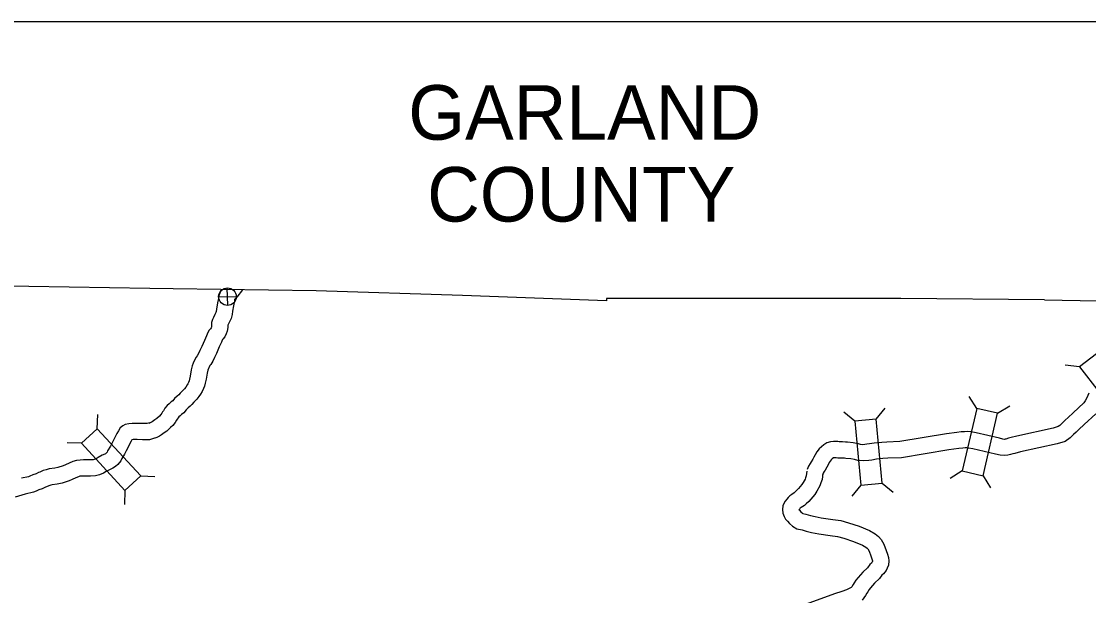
# Model space of a CAD drawing. Extents: x 1373862 to 1377080, y 1164775 to 1170415.
# Drawn here: x 1374006.5 to 1374204.1, y 1170282.4 to 1170388.8 of the extents above; entities that cross this region are included whole.
import ezdxf

# ---------------------------------------------------------------- set-up
doc = ezdxf.new("R2010")
doc.units = 0
doc.layers.add('1', color=7, linetype='Continuous')
doc.layers.add('Default', color=7, linetype='Continuous')

msp = doc.modelspace()

# ---------------------------------------------------------------- linework, layer by layer
at = {"layer": '1'}
msp.add_lwpolyline([(1373884.49, 1170388.77), (1374613.88, 1170388.77), (1374613.88, 1169861.94), (1373884.49, 1169861.94)], close=True, dxfattribs=at)
at = {"layer": 'Default'}
for p, q in [((1374044.67, 1170336.14), (1374044.59, 1170339.39)), ((1374043, 1170337.73), (1374046.26, 1170337.8)), ((1374202.39, 1170324.77), (1374199.77, 1170325.11)), ((1374183.39, 1170317.06), (1374181.99, 1170319.3)), ((1374160.79, 1170314.69), (1374158.76, 1170316.37)), ((1374164.74, 1170315.06), (1374166.42, 1170317.09)), ((1374187.24, 1170316.16), (1374189.49, 1170317.56)), ((1374020.51, 1170313.3), (1374020.61, 1170315.94)), ((1374017.6, 1170310.62), (1374014.96, 1170310.72)), ((1374028.56, 1170304.57), (1374031.2, 1170304.47)), ((1374180.69, 1170305.49), (1374178.45, 1170304.1)), ((1374184.55, 1170304.59), (1374185.94, 1170302.35)), ((1374161.9, 1170302.86), (1374160.22, 1170300.83)), ((1374165.85, 1170303.23), (1374167.88, 1170301.54)), ((1374025.65, 1170301.89), (1374025.55, 1170299.25))]:
    msp.add_line(p, q, dxfattribs=at)
for points in [[(1374030.27, 1170339.27), (1374007.88, 1170339.67), (1373981.34, 1170339.86), (1373952.41, 1170339.64), (1373952.43, 1170340.29), (1373926.15, 1170339.86), (1373899.6, 1170339.6), (1373884.49, 1170339.59)], [(1374043.63, 1170339.11), (1374043.44, 1170338.92), (1374043.21, 1170338.44), (1374043.09, 1170338.13), (1374043, 1170337.72), (1374042.96, 1170337.45), (1374042.78, 1170336.62), (1374042.59, 1170335.46), (1374042.55, 1170335.03), (1374042.48, 1170334.81), (1374042.31, 1170334.45), (1374042.04, 1170333.94), (1374041.85, 1170333.54), (1374041.69, 1170332.97), (1374041.68, 1170332.53), (1374041.69, 1170332.24), (1374041.67, 1170332.13), (1374041.67, 1170332.12), (1374041.59, 1170331.97), (1374041.48, 1170331.83), (1374041.24, 1170331.55), (1374041.01, 1170331.16), (1374040.88, 1170330.84), (1374040.75, 1170330.52), (1374040.36, 1170329.67), (1374040.13, 1170329.11), (1374039.86, 1170328.55), (1374039.51, 1170327.78), (1374039.26, 1170327.26), (1374038.99, 1170326.81), (1374038.83, 1170326.57), (1374038.46, 1170325.91), (1374038.27, 1170325.46), (1374038.11, 1170324.94), (1374037.93, 1170324.21), (1374037.74, 1170323.04), (1374037.63, 1170322.5), (1374037.53, 1170322.18), (1374037.41, 1170321.85), (1374037.31, 1170321.63), (1374037.17, 1170321.41), (1374036.9, 1170321.03), (1374036.65, 1170320.71), (1374036.27, 1170320.28), (1374035.88, 1170319.9), (1374035.6, 1170319.59), (1374035.32, 1170319.33), (1374034.85, 1170318.88), (1374034.49, 1170318.49), (1374034.22, 1170318.28), (1374033.81, 1170317.92), (1374033.46, 1170317.58), (1374033.06, 1170317.1), (1374032.77, 1170316.65), (1374032.63, 1170316.41), (1374032.49, 1170316.19), (1374032.28, 1170315.93), (1374032.02, 1170315.66), (1374031.54, 1170315.23), (1374031.18, 1170314.98), (1374030.67, 1170314.59), (1374030.56, 1170314.52), (1374030.29, 1170314.4), (1374030.04, 1170314.29)], [(1374195.9, 1170337.17), (1374169.32, 1170337.44), (1374142.6, 1170337.4), (1374114.83, 1170337.46), (1374114.82, 1170337), (1374088.12, 1170338.01), (1374061.06, 1170338.87), (1374034.57, 1170339.21), (1374030.27, 1170339.27)], [(1374047.43, 1170339.06), (1374046.37, 1170337.66), (1374045.96, 1170337.22), (1374045.95, 1170337.18), (1374045.92, 1170336.93), (1374045.73, 1170336.06), (1374045.56, 1170335.07), (1374045.51, 1170334.45), (1374045.29, 1170333.73), (1374045, 1170333.11), (1374044.73, 1170332.6), (1374044.68, 1170332.5), (1374044.69, 1170332.07), (1374044.6, 1170331.39), (1374044.41, 1170330.9), (1374044.12, 1170330.34), (1374043.79, 1170329.92), (1374043.7, 1170329.81), (1374043.67, 1170329.73), (1374043.51, 1170329.34), (1374043.12, 1170328.48), (1374042.87, 1170327.87), (1374042.57, 1170327.27), (1374042.23, 1170326.51), (1374041.9, 1170325.84), (1374041.53, 1170325.21), (1374041.38, 1170324.99), (1374041.16, 1170324.59), (1374041.09, 1170324.44), (1374041, 1170324.14), (1374040.88, 1170323.62), (1374040.69, 1170322.48), (1374040.53, 1170321.74), (1374040.37, 1170321.21), (1374040.19, 1170320.73), (1374039.96, 1170320.2), (1374039.65, 1170319.73), (1374039.32, 1170319.26), (1374038.96, 1170318.79), (1374038.43, 1170318.2), (1374038.04, 1170317.82), (1374037.75, 1170317.5), (1374037.38, 1170317.15), (1374036.99, 1170316.78), (1374036.53, 1170316.27), (1374036.13, 1170315.97), (1374035.85, 1170315.72), (1374035.65, 1170315.53), (1374035.49, 1170315.33), (1374035.33, 1170315.08), (1374035.2, 1170314.87), (1374034.95, 1170314.45), (1374034.52, 1170313.93), (1374034.11, 1170313.51), (1374033.39, 1170312.86), (1374032.93, 1170312.54), (1374032.42, 1170312.15), (1374032.03, 1170311.9), (1374031.53, 1170311.66), (1374031.27, 1170311.55)], [(1374195.9, 1170337.17), (1374218.92, 1170336.75)], [(1374204.15, 1170319.92), (1374203.94, 1170319.45), (1374203.71, 1170318.93), (1374203.47, 1170318.5), (1374203.18, 1170318.08), (1374201.23, 1170316.28), (1374200.28, 1170315.38), (1374199.71, 1170314.88), (1374199.18, 1170314.33), (1374198.76, 1170313.93), (1374198.42, 1170313.69), (1374197.5, 1170313.42), (1374190.79, 1170311.92), (1374189.77, 1170311.67), (1374189.22, 1170311.55), (1374188.76, 1170311.39), (1374188.64, 1170311.36), (1374188.47, 1170311.34), (1374188.19, 1170311.36), (1374187.58, 1170311.53), (1374183.23, 1170312.54), (1374182.26, 1170312.7), (1374181.67, 1170312.77), (1374181.08, 1170312.75), (1374180.51, 1170312.71), (1374179.7, 1170312.61), (1374177.76, 1170312.37), (1374169.13, 1170310.93), (1374166.74, 1170310.82), (1374165.78, 1170310.76), (1374165.09, 1170310.71), (1374164.36, 1170310.63), (1374163.53, 1170310.48), (1374163.03, 1170310.44), (1374162.27, 1170310.34), (1374161.87, 1170310.36), (1374161.48, 1170310.49), (1374160.47, 1170310.68), (1374159.45, 1170310.79), (1374159.06, 1170310.83), (1374158.51, 1170310.85), (1374157.89, 1170310.88), (1374157.63, 1170310.94), (1374156.84, 1170310.94), (1374156.27, 1170310.89), (1374155.62, 1170310.71), (1374155.05, 1170310.31), (1374154.62, 1170309.98), (1374154.2, 1170309.59), (1374153.76, 1170309.04), (1374153.42, 1170308.48), (1374153.19, 1170308.02), (1374153, 1170307.68), (1374152.71, 1170307.2), (1374152.52, 1170306.89), (1374152.22, 1170306.36), (1374151.99, 1170305.75)], [(1374030.5, 1170314.47), (1374029.79, 1170314.27), (1374028.96, 1170314.27), (1374027.91, 1170314.3), (1374027, 1170314.29), (1374026.39, 1170314.23), (1374025.67, 1170314.08), (1374025.27, 1170313.87), (1374024.79, 1170313.48), (1374024.43, 1170312.91), (1374024.15, 1170312.42), (1374023.21, 1170310.55), (1374022.97, 1170310.07), (1374022.43, 1170309.2), (1374022.33, 1170308.98), (1374022.16, 1170308.79), (1374022.04, 1170308.68), (1374021.95, 1170308.62), (1374021.46, 1170308.39), (1374020.72, 1170308), (1374020.31, 1170307.76), (1374019.97, 1170307.6), (1374019.79, 1170307.57), (1374019.18, 1170307.54), (1374018, 1170307.53), (1374017.33, 1170307.5), (1374016.69, 1170307.45), (1374015.98, 1170307.22), (1374015.34, 1170306.94), (1374014.64, 1170306.63), (1374014.21, 1170306.44), (1374013.24, 1170306.1), (1374012.67, 1170305.98), (1374011.6, 1170305.89), (1374011.06, 1170305.72), (1374010.52, 1170305.55), (1374009.88, 1170305.28), (1374009.67, 1170305.18), (1374009.18, 1170304.97), (1374008.61, 1170304.75), (1374008.05, 1170304.53), (1374007.8, 1170304.42), (1374006.51, 1170304.13)], [(1374205.44, 1170316.09), (1374203.28, 1170314.09), (1374202.3, 1170313.16), (1374201.77, 1170312.69), (1374201.3, 1170312.22), (1374200.67, 1170311.6), (1374199.72, 1170310.95), (1374198.26, 1170310.52), (1374191.47, 1170309), (1374190.43, 1170308.74), (1374190.04, 1170308.66), (1374189.6, 1170308.51), (1374189.15, 1170308.4), (1374188.55, 1170308.33), (1374187.69, 1170308.39), (1374186.85, 1170308.62), (1374182.64, 1170309.6), (1374181.85, 1170309.73), (1374181.53, 1170309.76), (1374181.23, 1170309.76), (1374180.81, 1170309.72), (1374180.06, 1170309.63), (1374178.19, 1170309.4), (1374169.44, 1170307.94), (1374166.9, 1170307.83), (1374165.99, 1170307.77), (1374165.38, 1170307.72), (1374164.78, 1170307.66), (1374163.93, 1170307.51), (1374163.36, 1170307.45), (1374162.38, 1170307.33), (1374161.33, 1170307.39), (1374160.73, 1170307.58), (1374160.03, 1170307.71), (1374159.14, 1170307.81), (1374158.85, 1170307.84), (1374158.39, 1170307.86), (1374157.65, 1170307.88), (1374157.34, 1170307.92), (1374157.25, 1170307.94), (1374156.99, 1170307.94), (1374156.88, 1170307.93), (1374156.83, 1170307.9), (1374156.57, 1170307.7), (1374156.42, 1170307.56), (1374156.23, 1170307.32), (1374156.05, 1170307.02), (1374155.84, 1170306.6), (1374155.59, 1170306.16), (1374155.27, 1170305.64), (1374155.1, 1170305.36), (1374154.95, 1170305.09), (1374154.8, 1170304.69)], [(1374031.32, 1170311.59), (1374030.2, 1170311.27), (1374028.92, 1170311.27), (1374027.88, 1170311.3), (1374027.17, 1170311.3), (1374026.95, 1170311.27), (1374026.81, 1170311.01), (1374025.89, 1170309.2), (1374025.59, 1170308.61), (1374025.08, 1170307.78), (1374024.87, 1170307.33), (1374024.3, 1170306.69), (1374023.92, 1170306.33), (1374023.43, 1170306), (1374022.78, 1170305.7), (1374022.18, 1170305.38), (1374021.7, 1170305.1), (1374020.93, 1170304.74), (1374020.18, 1170304.58), (1374019.26, 1170304.54), (1374018.07, 1170304.53), (1374017.52, 1170304.51), (1374017.28, 1170304.49), (1374017.04, 1170304.41), (1374016.55, 1170304.19), (1374015.87, 1170303.89), (1374015.33, 1170303.65), (1374014.04, 1170303.2), (1374013.11, 1170303.01), (1374012.18, 1170302.93), (1374011.95, 1170302.86), (1374011.56, 1170302.73), (1374011.1, 1170302.54), (1374010.91, 1170302.45), (1374010.32, 1170302.2), (1374009.71, 1170301.96), (1374009.2, 1170301.76), (1374008.74, 1170301.55), (1374007.15, 1170301.2)], [(1374151.91, 1170305.45), (1374151.79, 1170304.59), (1374151.66, 1170304.19), (1374151.58, 1170303.95), (1374151.24, 1170303.33), (1374150.98, 1170302.97), (1374150.38, 1170302.23), (1374150.14, 1170301.97), (1374149.72, 1170301.59), (1374149.56, 1170301.44), (1374149.13, 1170301.15), (1374148.78, 1170300.88), (1374148.43, 1170300.56), (1374148.18, 1170300.28), (1374147.88, 1170299.86), (1374147.63, 1170299.43), (1374147.47, 1170299), (1374147.37, 1170298.37), (1374147.46, 1170297.65), (1374147.68, 1170297.07), (1374147.97, 1170296.58), (1374148.33, 1170296.16), (1374148.71, 1170295.76), (1374149.25, 1170295.28), (1374150.04, 1170294.77), (1374151.02, 1170294.58), (1374151.77, 1170294.36), (1374152.8, 1170294.1), (1374154.1, 1170293.86), (1374156.24, 1170293.55), (1374157.58, 1170293.34), (1374158.75, 1170293.02), (1374160.55, 1170292.43), (1374162.2, 1170291.74), (1374162.85, 1170291.38), (1374163.07, 1170291.19), (1374163.22, 1170291.03), (1374163.45, 1170290.64), (1374163.78, 1170289.78), (1374163.95, 1170289.2), (1374164.06, 1170288.83), (1374164.07, 1170288.76), (1374164.07, 1170288.74), (1374164.02, 1170288.65), (1374163.86, 1170288.43), (1374163.56, 1170288.14), (1374163.12, 1170287.56), (1374162.29, 1170286.75), (1374161.4, 1170285.76), (1374161, 1170285.26), (1374160.69, 1170284.76), (1374160.47, 1170284.46), (1374160.22, 1170284.03), (1374160.12, 1170283.88), (1374159.28, 1170283.44), (1374158.36, 1170283.13), (1374157.05, 1170282.71), (1374151.79, 1170280.78)], [(1374154.88, 1170305), (1374154.72, 1170303.91), (1374154.51, 1170303.27), (1374154.34, 1170302.75), (1374153.78, 1170301.72), (1374153.36, 1170301.15), (1374152.66, 1170300.28), (1374152.27, 1170299.84), (1374151.76, 1170299.39), (1374151.46, 1170299.1), (1374150.86, 1170298.7), (1374150.7, 1170298.58), (1374150.59, 1170298.47), (1374150.52, 1170298.39), (1374150.45, 1170298.3), (1374150.55, 1170298.19), (1374150.81, 1170297.91), (1374151.08, 1170297.66), (1374151.18, 1170297.6), (1374151.72, 1170297.5), (1374152.56, 1170297.26), (1374153.45, 1170297.03), (1374154.59, 1170296.82), (1374156.69, 1170296.52), (1374158.2, 1170296.28), (1374159.61, 1170295.9), (1374161.6, 1170295.24), (1374163.5, 1170294.45), (1374164.58, 1170293.86), (1374165.18, 1170293.34), (1374165.66, 1170292.81), (1374166.16, 1170291.94), (1374166.62, 1170290.74), (1374166.82, 1170290.05), (1374167, 1170289.46), (1374167.08, 1170288.85), (1374167.03, 1170288.03), (1374166.79, 1170287.49), (1374166.58, 1170287.06), (1374166.11, 1170286.45), (1374165.82, 1170286.15), (1374165.37, 1170285.57), (1374164.46, 1170284.68), (1374163.69, 1170283.82), (1374163.45, 1170283.52), (1374163.18, 1170283.08), (1374162.99, 1170282.82), (1374162.76, 1170282.42), (1374162.15, 1170281.56)], [(1374005.39, 1170300.7), (1374007.24, 1170301.22)]]:
    msp.add_lwpolyline(points, dxfattribs=at)
for points in [[(1374212.78, 1170317.79), (1374205.52, 1170327.19), (1374202.39, 1170324.77), (1374209.65, 1170315.37)], [(1374184.55, 1170304.59), (1374187.24, 1170316.16), (1374183.39, 1170317.06), (1374180.69, 1170305.49)], [(1374160.79, 1170314.69), (1374161.9, 1170302.86), (1374165.85, 1170303.23), (1374164.74, 1170315.06)], [(1374028.56, 1170304.57), (1374020.51, 1170313.3), (1374017.6, 1170310.62), (1374025.65, 1170301.89)]]:
    msp.add_lwpolyline(points, close=True, dxfattribs=at)
msp.add_circle((1374044.63, 1170337.77), 1.63, dxfattribs=at)

# ---------------------------------------------------------------- texts
for s, p in [('GARLAND', (1374078.11, 1170366.84)), ('COUNTY', (1374081.6, 1170351.68))]:
    msp.add_text(s, height=10.107, dxfattribs=at).set_placement(p)

doc.saveas('drawing.dxf')
